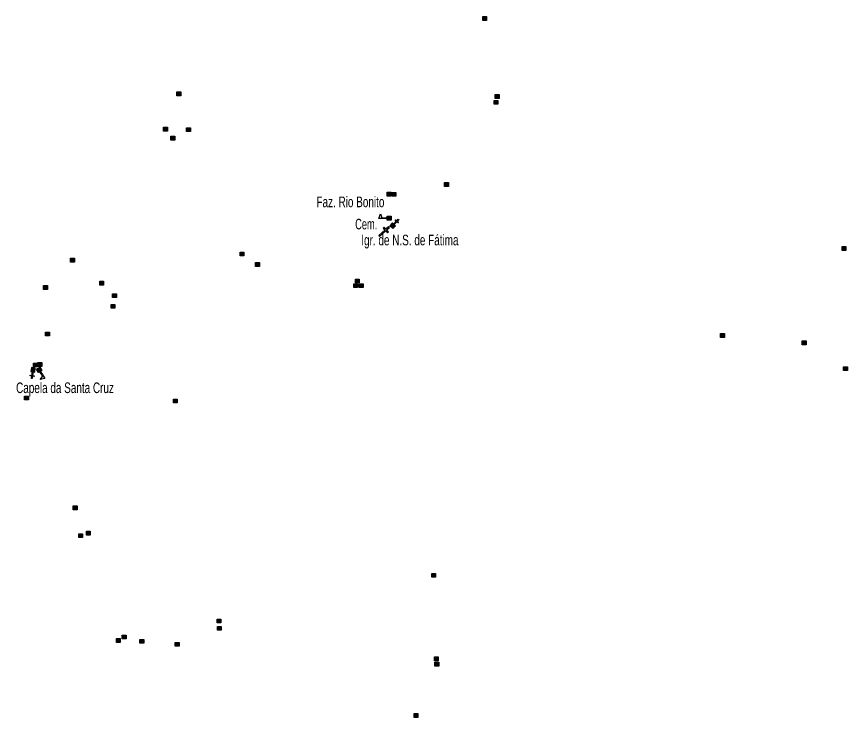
# Model space of a CAD drawing. Extents: x 647.8 to 672.9, y 6929.3 to 6957.3.
# Drawn here: x 660.4 to 666.66, y 6951.45 to 6956.73 of the extents above; entities that cross this region are included whole.
import ezdxf
from ezdxf.enums import TextEntityAlignment as Align

# ---------------------------------------------------------------- set-up
doc = ezdxf.new("R2010")
doc.units = 0
doc.header["$LTSCALE"] = 0.032
for name, color, linetype, lineweight in [('2', 7, 'Continuous', 25), ('20', 7, 'Continuous', 25), ('4', 7, 'Continuous', 25), ('6', 7, 'Continuous', 25)]:
    doc.layers.add(name, color=color, linetype=linetype, lineweight=lineweight)
doc.layers.add('61', color=7, linetype='Continuous')

msp = doc.modelspace()

# ---------------------------------------------------------------- hatches: boundary and pattern name
at = {"layer": '2'}
for points in [[(663.9137, 6956.7299), (663.9427, 6956.7299), (663.9427, 6956.7009), (663.9137, 6956.7009)], [(661.6101, 6956.1617), (661.6391, 6956.1617), (661.6391, 6956.1327), (661.6101, 6956.1327)], [(664.008, 6956.142), (664.037, 6956.142), (664.037, 6956.113), (664.008, 6956.113)], [(663.9992, 6956.0981), (664.0282, 6956.0981), (664.0282, 6956.0691), (663.9992, 6956.0691)], [(661.5092, 6955.8963), (661.5382, 6955.8963), (661.5382, 6955.8673), (661.5092, 6955.8673)], [(661.6825, 6955.8919), (661.7115, 6955.8919), (661.7115, 6955.8629), (661.6825, 6955.8629)], [(661.5641, 6955.8282), (661.5931, 6955.8282), (661.5931, 6955.7992), (661.5641, 6955.7992)], [(663.6263, 6955.4794), (663.6553, 6955.4794), (663.6553, 6955.4504), (663.6263, 6955.4504)], [(663.1945, 6955.4061), (663.2235, 6955.4061), (663.2235, 6955.3771), (663.1945, 6955.3771)], [(663.2304, 6955.4044), (663.2594, 6955.4044), (663.2594, 6955.3754), (663.2304, 6955.3754)], [(662.0862, 6954.9551), (662.1152, 6954.9551), (662.1152, 6954.9261), (662.0862, 6954.9261)], [(666.6209, 6954.9968), (666.6499, 6954.9968), (666.6499, 6954.9678), (666.6209, 6954.9678)], [(660.8094, 6954.909), (660.8384, 6954.909), (660.8384, 6954.88), (660.8094, 6954.88)], [(662.2025, 6954.8761), (662.2315, 6954.8761), (662.2315, 6954.8471), (662.2025, 6954.8471)], [(660.6054, 6954.7028), (660.6344, 6954.7028), (660.6344, 6954.6738), (660.6054, 6954.6738)], [(661.0288, 6954.7357), (661.0578, 6954.7357), (661.0578, 6954.7067), (661.0288, 6954.7067)], [(662.9418, 6954.716), (662.9708, 6954.716), (662.9708, 6954.687), (662.9418, 6954.687)], [(662.955, 6954.7511), (662.984, 6954.7511), (662.984, 6954.7221), (662.955, 6954.7221)], [(662.9835, 6954.716), (663.0125, 6954.716), (663.0125, 6954.687), (662.9835, 6954.687)], [(661.1253, 6954.6414), (661.1543, 6954.6414), (661.1543, 6954.6124), (661.1253, 6954.6124)], [(661.1143, 6954.5602), (661.1433, 6954.5602), (661.1433, 6954.5312), (661.1143, 6954.5312)], [(660.6207, 6954.3518), (660.6497, 6954.3518), (660.6497, 6954.3228), (660.6207, 6954.3228)], [(665.7061, 6954.3408), (665.7351, 6954.3408), (665.7351, 6954.3118), (665.7061, 6954.3118)], [(666.3203, 6954.286), (666.3493, 6954.286), (666.3493, 6954.257), (666.3203, 6954.257)], [(660.5284, 6954.118), (660.5574, 6954.118), (660.5574, 6954.089), (660.5284, 6954.089)], [(660.5624, 6954.1222), (660.5914, 6954.1222), (660.5914, 6954.0932), (660.5624, 6954.0932)], [(666.6319, 6954.0907), (666.6609, 6954.0907), (666.6609, 6954.0617), (666.6319, 6954.0617)], [(660.4628, 6953.8691), (660.4918, 6953.8691), (660.4918, 6953.8401), (660.4628, 6953.8401)], [(661.5838, 6953.8472), (661.6128, 6953.8472), (661.6128, 6953.8182), (661.5838, 6953.8182)], [(660.8291, 6953.0421), (660.8581, 6953.0421), (660.8581, 6953.0131), (660.8291, 6953.0131)], [(660.8708, 6952.8315), (660.8998, 6952.8315), (660.8998, 6952.8025), (660.8708, 6952.8025)], [(660.9279, 6952.8512), (660.9569, 6952.8512), (660.9569, 6952.8222), (660.9279, 6952.8222)], [(663.5298, 6952.5331), (663.5588, 6952.5331), (663.5588, 6952.5041), (663.5298, 6952.5041)], [(661.9129, 6952.1887), (661.9419, 6952.1887), (661.9419, 6952.1597), (661.9129, 6952.1597)], [(661.9151, 6952.1338), (661.9441, 6952.1338), (661.9441, 6952.1048), (661.9151, 6952.1048)], [(661.1977, 6952.068), (661.2267, 6952.068), (661.2267, 6952.039), (661.1977, 6952.039)], [(661.1538, 6952.0417), (661.1828, 6952.0417), (661.1828, 6952.0127), (661.1538, 6952.0127)], [(661.3315, 6952.0351), (661.3605, 6952.0351), (661.3605, 6952.0061), (661.3315, 6952.0061)], [(661.597, 6952.0131), (661.626, 6952.0131), (661.626, 6951.9841), (661.597, 6951.9841)], [(663.5495, 6951.9035), (663.5785, 6951.9035), (663.5785, 6951.8745), (663.5495, 6951.8745)], [(663.5539, 6951.864), (663.5829, 6951.864), (663.5829, 6951.835), (663.5539, 6951.835)], [(663.3964, 6951.4767), (663.4254, 6951.4767), (663.4254, 6951.4477), (663.3964, 6951.4477)]]:
    msp.add_hatch(color=256, dxfattribs=at).paths.add_polyline_path(points)
at = {"layer": '4'}
for points in [[(663.223, 6955.1947), (663.193, 6955.1949), (663.1932, 6955.2249), (663.2232, 6955.2247)], [(660.5777, 6954.0882), (660.5933, 6954.0626), (660.5677, 6954.047), (660.5521, 6954.0726)]]:
    msp.add_hatch(color=256, dxfattribs=at).paths.add_polyline_path(points)
at = {"layer": '6'}
for points in [[(663.2478, 6955.1625), (663.2441, 6955.1659), (663.2627, 6955.1862), (663.2534, 6955.1946), (663.2568, 6955.1983), (663.266, 6955.1899), (663.2778, 6955.2028), (663.2815, 6955.1994), (663.2697, 6955.1865), (663.279, 6955.178), (663.2756, 6955.1744), (663.2664, 6955.1828)], [(663.2349, 6955.1743), (663.2146, 6955.1522), (663.2368, 6955.1319), (663.257, 6955.1541)], [(660.5388, 6954.0502), (660.5432, 6954.0799), (660.5135, 6954.0842), (660.5091, 6954.0545)], [(660.5215, 6954.0527), (660.5264, 6954.052), (660.5224, 6954.0248), (660.5347, 6954.023), (660.534, 6954.018), (660.5217, 6954.0199), (660.5191, 6954.0026), (660.5142, 6954.0033), (660.5167, 6954.0206), (660.5043, 6954.0224), (660.5051, 6954.0274), (660.5174, 6954.0255)]]:
    msp.add_hatch(color=256, dxfattribs=at).paths.add_polyline_path(points)

# ---------------------------------------------------------------- linework, layer by layer
at = {"layer": '2'}
for points in [[(663.9137, 6956.7299), (663.9427, 6956.7299), (663.9427, 6956.7009), (663.9137, 6956.7009)], [(661.6101, 6956.1617), (661.6391, 6956.1617), (661.6391, 6956.1327), (661.6101, 6956.1327)], [(664.008, 6956.142), (664.037, 6956.142), (664.037, 6956.113), (664.008, 6956.113)], [(663.9992, 6956.0981), (664.0282, 6956.0981), (664.0282, 6956.0691), (663.9992, 6956.0691)], [(661.5092, 6955.8963), (661.5382, 6955.8963), (661.5382, 6955.8673), (661.5092, 6955.8673)], [(661.6825, 6955.8919), (661.7115, 6955.8919), (661.7115, 6955.8629), (661.6825, 6955.8629)], [(661.5641, 6955.8282), (661.5931, 6955.8282), (661.5931, 6955.7992), (661.5641, 6955.7992)], [(663.6263, 6955.4794), (663.6553, 6955.4794), (663.6553, 6955.4504), (663.6263, 6955.4504)], [(663.1945, 6955.4061), (663.2235, 6955.4061), (663.2235, 6955.3771), (663.1945, 6955.3771)], [(663.2304, 6955.4044), (663.2594, 6955.4044), (663.2594, 6955.3754), (663.2304, 6955.3754)], [(662.0862, 6954.9551), (662.1152, 6954.9551), (662.1152, 6954.9261), (662.0862, 6954.9261)], [(666.6209, 6954.9968), (666.6499, 6954.9968), (666.6499, 6954.9678), (666.6209, 6954.9678)], [(660.8094, 6954.909), (660.8384, 6954.909), (660.8384, 6954.88), (660.8094, 6954.88)], [(662.2025, 6954.8761), (662.2315, 6954.8761), (662.2315, 6954.8471), (662.2025, 6954.8471)], [(660.6054, 6954.7028), (660.6344, 6954.7028), (660.6344, 6954.6738), (660.6054, 6954.6738)], [(661.0288, 6954.7357), (661.0578, 6954.7357), (661.0578, 6954.7067), (661.0288, 6954.7067)], [(662.9418, 6954.716), (662.9708, 6954.716), (662.9708, 6954.687), (662.9418, 6954.687)], [(662.955, 6954.7511), (662.984, 6954.7511), (662.984, 6954.7221), (662.955, 6954.7221)], [(662.9835, 6954.716), (663.0125, 6954.716), (663.0125, 6954.687), (662.9835, 6954.687)], [(661.1253, 6954.6414), (661.1543, 6954.6414), (661.1543, 6954.6124), (661.1253, 6954.6124)], [(661.1143, 6954.5602), (661.1433, 6954.5602), (661.1433, 6954.5312), (661.1143, 6954.5312)], [(660.6207, 6954.3518), (660.6497, 6954.3518), (660.6497, 6954.3228), (660.6207, 6954.3228)], [(665.7061, 6954.3408), (665.7351, 6954.3408), (665.7351, 6954.3118), (665.7061, 6954.3118)], [(666.3203, 6954.286), (666.3493, 6954.286), (666.3493, 6954.257), (666.3203, 6954.257)], [(660.5284, 6954.118), (660.5574, 6954.118), (660.5574, 6954.089), (660.5284, 6954.089)], [(660.5624, 6954.1222), (660.5914, 6954.1222), (660.5914, 6954.0932), (660.5624, 6954.0932)], [(666.6319, 6954.0907), (666.6609, 6954.0907), (666.6609, 6954.0617), (666.6319, 6954.0617)], [(660.4628, 6953.8691), (660.4918, 6953.8691), (660.4918, 6953.8401), (660.4628, 6953.8401)], [(661.5838, 6953.8472), (661.6128, 6953.8472), (661.6128, 6953.8182), (661.5838, 6953.8182)], [(660.8291, 6953.0421), (660.8581, 6953.0421), (660.8581, 6953.0131), (660.8291, 6953.0131)], [(660.8708, 6952.8315), (660.8998, 6952.8315), (660.8998, 6952.8025), (660.8708, 6952.8025)], [(660.9279, 6952.8512), (660.9569, 6952.8512), (660.9569, 6952.8222), (660.9279, 6952.8222)], [(663.5298, 6952.5331), (663.5588, 6952.5331), (663.5588, 6952.5041), (663.5298, 6952.5041)], [(661.9129, 6952.1887), (661.9419, 6952.1887), (661.9419, 6952.1597), (661.9129, 6952.1597)], [(661.9151, 6952.1338), (661.9441, 6952.1338), (661.9441, 6952.1048), (661.9151, 6952.1048)], [(661.1977, 6952.068), (661.2267, 6952.068), (661.2267, 6952.039), (661.1977, 6952.039)], [(661.1538, 6952.0417), (661.1828, 6952.0417), (661.1828, 6952.0127), (661.1538, 6952.0127)], [(661.3315, 6952.0351), (661.3605, 6952.0351), (661.3605, 6952.0061), (661.3315, 6952.0061)], [(661.597, 6952.0131), (661.626, 6952.0131), (661.626, 6951.9841), (661.597, 6951.9841)], [(663.5495, 6951.9035), (663.5785, 6951.9035), (663.5785, 6951.8745), (663.5495, 6951.8745)], [(663.5539, 6951.864), (663.5829, 6951.864), (663.5829, 6951.835), (663.5539, 6951.835)], [(663.3964, 6951.4767), (663.4254, 6951.4767), (663.4254, 6951.4477), (663.3964, 6951.4477)]]:
    msp.add_lwpolyline(points, close=True, dxfattribs=at)
at = {"layer": '20'}
for points in [[(663.1844, 6955.1274), (663.1709, 6955.1422), (663.1646, 6955.1364), (663.1781, 6955.1217), (663.1313, 6955.0788)], [(663.1898, 6955.1215), (663.2105, 6955.1404), (663.2051, 6955.1463), (663.1844, 6955.1274)], [(663.1313, 6955.0788), (663.1366, 6955.0729), (663.1835, 6955.1158)], [(663.1835, 6955.1158), (663.197, 6955.101), (663.2033, 6955.1067), (663.1898, 6955.1215)]]:
    msp.add_lwpolyline(points, dxfattribs=at)
at = {"layer": '4'}
for p, q in [((663.1931, 6955.2074), (663.1931, 6955.2124)), ((660.5826, 6954.0561), (660.5783, 6954.0535))]:
    msp.add_line(p, q, dxfattribs=at)
for points in [[(663.1931, 6955.2074), (663.1306, 6955.2078), (663.1433, 6955.2427), (663.1536, 6955.2127), (663.1931, 6955.2124)], [(663.223, 6955.1947), (663.193, 6955.1949), (663.1932, 6955.2249), (663.2232, 6955.2247)], [(660.5777, 6954.0882), (660.5933, 6954.0626), (660.5677, 6954.047), (660.5521, 6954.0726)], [(660.5826, 6954.0561), (660.6151, 6954.0027), (660.5787, 6953.9952), (660.5989, 6954.0197), (660.5783, 6954.0535)]]:
    msp.add_lwpolyline(points, close=True, dxfattribs=at)
at = {"layer": '6'}
for points in [[(663.2478, 6955.1625), (663.2441, 6955.1659), (663.2627, 6955.1862), (663.2534, 6955.1946), (663.2568, 6955.1983), (663.266, 6955.1899), (663.2778, 6955.2028), (663.2815, 6955.1994), (663.2697, 6955.1865), (663.279, 6955.178), (663.2756, 6955.1744), (663.2664, 6955.1828)], [(663.2349, 6955.1743), (663.2146, 6955.1522), (663.2368, 6955.1319), (663.257, 6955.1541)], [(660.5388, 6954.0502), (660.5432, 6954.0799), (660.5135, 6954.0842), (660.5091, 6954.0545)], [(660.5215, 6954.0527), (660.5264, 6954.052), (660.5224, 6954.0248), (660.5347, 6954.023), (660.534, 6954.018), (660.5217, 6954.0199), (660.5191, 6954.0026), (660.5142, 6954.0033), (660.5167, 6954.0206), (660.5043, 6954.0224), (660.5051, 6954.0274), (660.5174, 6954.0255)]]:
    msp.add_lwpolyline(points, close=True, dxfattribs=at)

# ---------------------------------------------------------------- texts
at = {"layer": '61'}
for s, width, p in [('Faz. Rio Bonito', 0.7, (663.173, 6955.2932)), ('Cem.', 0.65, (663.1191, 6955.1261))]:
    msp.add_text(s, height=0.08, dxfattribs=dict(at, width=width)).set_placement(p, align=Align.RIGHT)
at = {"layer": '61', "width": 0.7}
for s, p in [('Igr. de N.S. de Fátima', (662.999, 6955.0059)), ('Capela da Santa Cruz', (660.3986, 6953.8923))]:
    msp.add_text(s, height=0.08, dxfattribs=at).set_placement(p)

doc.saveas('drawing.dxf')
